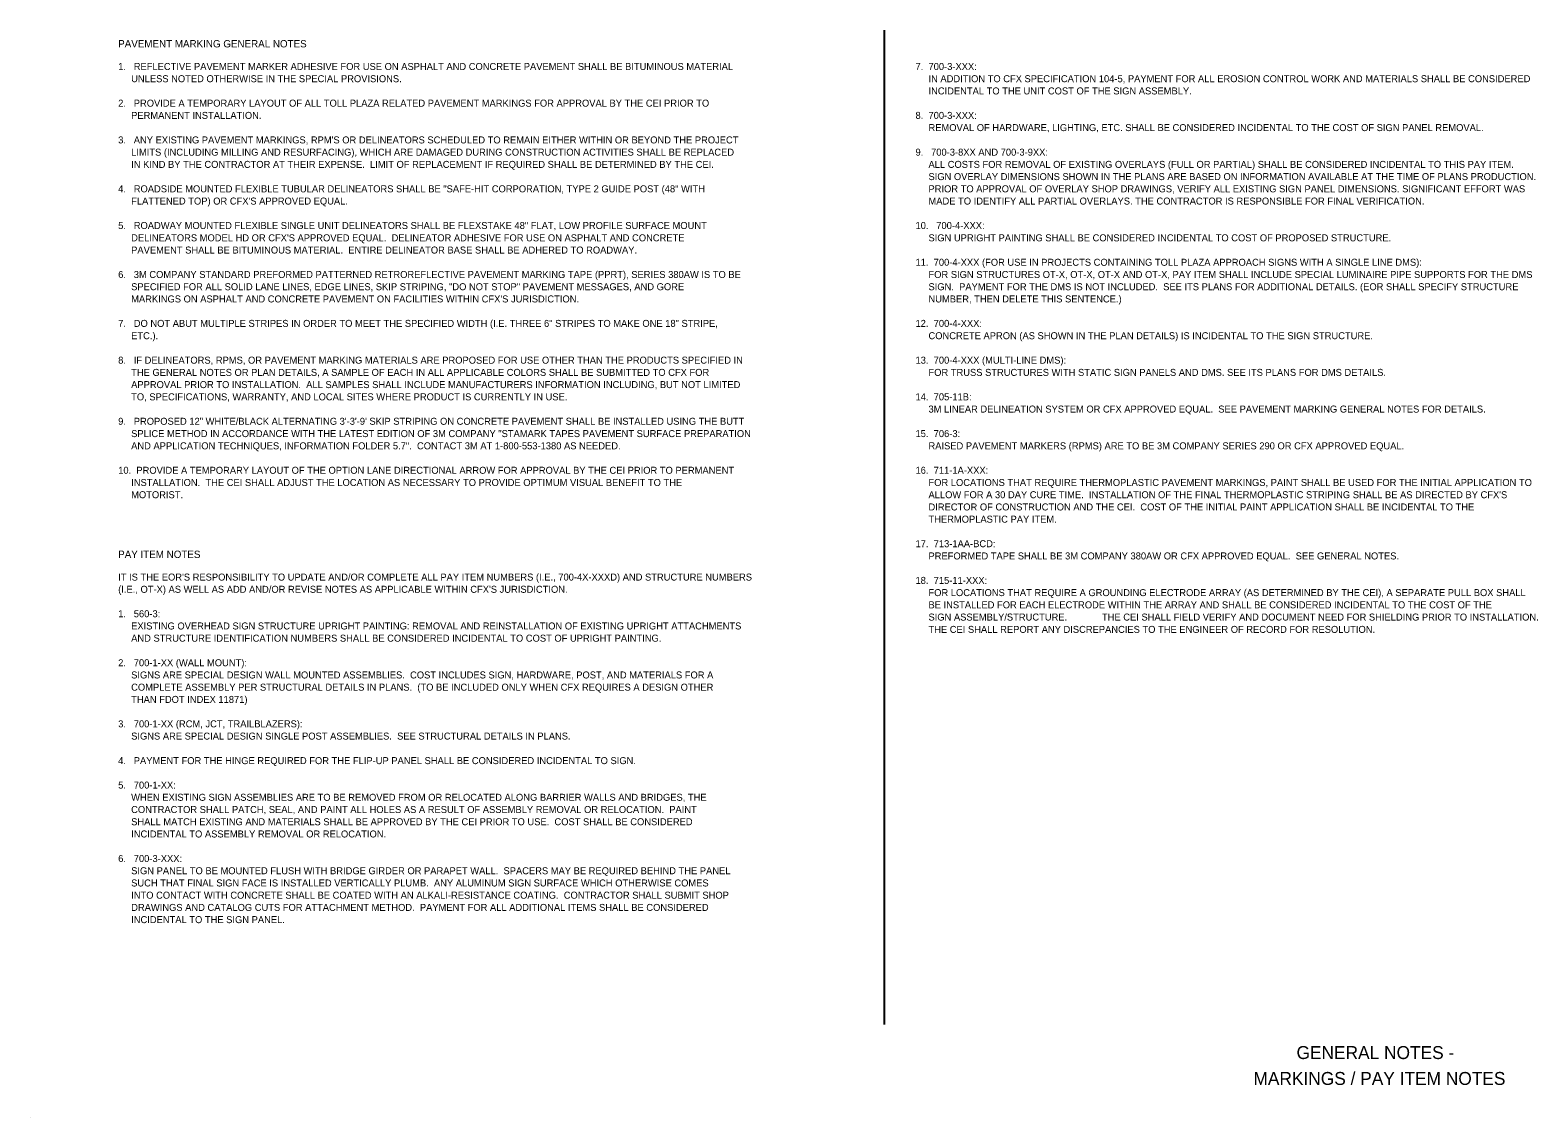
# Model space of a CAD drawing. Extents: x 2479959 to 2482822, y 3677554 to 3678604.
# Drawn here: x 2479959 to 2481415, y 3677554 to 3678604 of the extents above; entities that cross this region are included whole.
import ezdxf

# ---------------------------------------------------------------- set-up
doc = ezdxf.new("R2010")
doc.units = 0
for name, color, linetype in [('AdhocPoint_dp', 7, 'Continuous'), ('NonPlottingEle_dp', 7, 'Continuous'), ('TextLabel', 7, 'Continuous'), ('TextMisc', 7, 'Continuous')]:
    doc.layers.add(name, color=color, linetype=linetype)

msp = doc.modelspace()

# ---------------------------------------------------------------- linework, layer by layer
at = {"layer": 'AdhocPoint_dp'}
msp.add_line((2479959.3, 3677553.8), (2479959.3, 3677553.8), dxfattribs=at)
at = {"layer": 'NonPlottingEle_dp'}
msp.add_line((2480784.3, 3677643.8), (2480784.3, 3678603.8), dxfattribs=at)

# ---------------------------------------------------------------- texts
at = {"layer": 'TextLabel'}
for s, height, p in [('PAVEMENT MARKING GENERAL NOTES', 7.08, (2480044.3, 3678587.2)), ('1.   REFLECTIVE PAVEMENT MARKER ADHESIVE FOR USE ON ASPHALT AND CONCRETE PAVEMENT SHALL BE BITUMINOUS MATERIAL', 6.75, (2480044.3, 3678565.4)), ('7.  700-3-XXX:', 6.75, (2480814.3, 3678565.4)), ('     UNLESS NOTED OTHERWISE IN THE SPECIAL PROVISIONS.', 6.75, (2480044.3, 3678553.6)), ('     IN ADDITION TO CFX SPECIFICATION 104-5, PAYMENT FOR ALL EROSION CONTROL WORK AND MATERIALS SHALL BE CONSIDERED', 6.75, (2480814.3, 3678553.6)), ('     INCIDENTAL TO THE UNIT COST OF THE SIGN ASSEMBLY.', 6.75, (2480814.3, 3678541.8)), ('2.   PROVIDE A TEMPORARY LAYOUT OF ALL TOLL PLAZA RELATED PAVEMENT MARKINGS FOR APPROVAL BY THE CEI PRIOR TO', 6.75, (2480044.3, 3678530)), ('     PERMANENT INSTALLATION.', 6.75, (2480044.3, 3678518.2)), ('8.  700-3-XXX:', 6.75, (2480814.3, 3678518.2)), ('     REMOVAL OF HARDWARE, LIGHTING, ETC. SHALL BE CONSIDERED INCIDENTAL TO THE COST OF SIGN PANEL REMOVAL.', 6.75, (2480814.3, 3678506.4)), ("3.   ANY EXISTING PAVEMENT MARKINGS, RPM'S OR DELINEATORS SCHEDULED TO REMAIN EITHER WITHIN OR BEYOND THE PROJECT", 6.75, (2480044.3, 3678494.5)), ('     LIMITS (INCLUDING MILLING AND RESURFACING), WHICH ARE DAMAGED DURING CONSTRUCTION ACTIVITIES SHALL BE REPLACED', 6.75, (2480044.3, 3678482.7)), ('9.   700-3-8XX AND 700-3-9XX:', 6.75, (2480814.3, 3678482.7)), ('     IN KIND BY THE CONTRACTOR AT THEIR EXPENSE.  LIMIT OF REPLACEMENT IF REQUIRED SHALL BE DETERMINED BY THE CEI.', 6.75, (2480044.3, 3678470.9)), ('     ALL COSTS FOR REMOVAL OF EXISTING OVERLAYS (FULL OR PARTIAL) SHALL BE CONSIDERED INCIDENTAL TO THIS PAY ITEM. ', 6.75, (2480814.3, 3678470.9)), ('     SIGN OVERLAY DIMENSIONS SHOWN IN THE PLANS ARE BASED ON INFORMATION AVAILABLE AT THE TIME OF PLANS PRODUCTION.  ', 6.75, (2480814.3, 3678459.1)), ('4.   ROADSIDE MOUNTED FLEXIBLE TUBULAR DELINEATORS SHALL BE "SAFE-HIT CORPORATION, TYPE 2 GUIDE POST (48" WITH', 6.75, (2480044.3, 3678447.3)), ('     PRIOR TO APPROVAL OF OVERLAY SHOP DRAWINGS, VERIFY ALL EXISTING SIGN PANEL DIMENSIONS. SIGNIFICANT EFFORT WAS ', 6.75, (2480814.3, 3678447.3)), ("     FLATTENED TOP) OR CFX'S APPROVED EQUAL.", 6.75, (2480044.3, 3678435.5)), ('     MADE TO IDENTIFY ALL PARTIAL OVERLAYS. THE CONTRACTOR IS RESPONSIBLE FOR FINAL VERIFICATION. ', 6.75, (2480814.3, 3678435.5)), ('5.   ROADWAY MOUNTED FLEXIBLE SINGLE UNIT DELINEATORS SHALL BE FLEXSTAKE 48" FLAT, LOW PROFILE SURFACE MOUNT', 6.75, (2480044.3, 3678411.9)), ("     DELINEATORS MODEL HD OR CFX'S APPROVED EQUAL.  DELINEATOR ADHESIVE FOR USE ON ASPHALT AND CONCRETE", 6.75, (2480044.3, 3678400)), ('10.   700-4-XXX:', 6.75, (2480814.3, 3678411.9)), ('     SIGN UPRIGHT PAINTING SHALL BE CONSIDERED INCIDENTAL TO COST OF PROPOSED STRUCTURE.', 6.75, (2480814.3, 3678400)), ('     PAVEMENT SHALL BE BITUMINOUS MATERIAL.  ENTIRE DELINEATOR BASE SHALL BE ADHERED TO ROADWAY.', 6.75, (2480044.3, 3678388.2)), ('11.  700-4-XXX (FOR USE IN PROJECTS CONTAINING TOLL PLAZA APPROACH SIGNS WITH A SINGLE LINE DMS):', 6.75, (2480814.3, 3678376.4)), ('6.   3M COMPANY STANDARD PREFORMED PATTERNED RETROREFLECTIVE PAVEMENT MARKING TAPE (PPRT), SERIES 380AW IS TO BE', 6.75, (2480044.3, 3678364.6)), ('     FOR SIGN STRUCTURES OT-X, OT-X, OT-X AND OT-X, PAY ITEM SHALL INCLUDE SPECIAL LUMINAIRE PIPE SUPPORTS FOR THE DMS', 6.75, (2480814.3, 3678364.6)), ('     SPECIFIED FOR ALL SOLID LANE LINES, EDGE LINES, SKIP STRIPING, "DO NOT STOP" PAVEMENT MESSAGES, AND GORE', 6.75, (2480044.3, 3678352.8)), ('     SIGN.  PAYMENT FOR THE DMS IS NOT INCLUDED.  SEE ITS PLANS FOR ADDITIONAL DETAILS. (EOR SHALL SPECIFY STRUCTURE ', 6.75, (2480814.3, 3678352.8)), ("     MARKINGS ON ASPHALT AND CONCRETE PAVEMENT ON FACILITIES WITHIN CFX'S JURISDICTION.", 6.75, (2480044.3, 3678341)), ('     NUMBER, THEN DELETE THIS SENTENCE.)', 6.75, (2480814.3, 3678341)), ('7.   DO NOT ABUT MULTIPLE STRIPES IN ORDER TO MEET THE SPECIFIED WIDTH (I.E. THREE 6" STRIPES TO MAKE ONE 18" STRIPE,', 6.75, (2480044.3, 3678317.4)), ('12.  700-4-XXX:', 6.75, (2480814.3, 3678317.4)), ('     ETC.).', 6.75, (2480044.3, 3678305.5)), ('     CONCRETE APRON (AS SHOWN IN THE PLAN DETAILS) IS INCIDENTAL TO THE SIGN STRUCTURE. ', 6.75, (2480814.3, 3678305.5)), ('8.   IF DELINEATORS, RPMS, OR PAVEMENT MARKING MATERIALS ARE PROPOSED FOR USE OTHER THAN THE PRODUCTS SPECIFIED IN', 6.75, (2480044.3, 3678281.9)), ('     THE GENERAL NOTES OR PLAN DETAILS, A SAMPLE OF EACH IN ALL APPLICABLE COLORS SHALL BE SUBMITTED TO CFX FOR', 6.75, (2480044.3, 3678270.1)), ('13.  700-4-XXX (MULTI-LINE DMS):', 6.75, (2480814.3, 3678281.9)), ('     FOR TRUSS STRUCTURES WITH STATIC SIGN PANELS AND DMS. SEE ITS PLANS FOR DMS DETAILS.', 6.75, (2480814.3, 3678270.1)), ('     APPROVAL PRIOR TO INSTALLATION.  ALL SAMPLES SHALL INCLUDE MANUFACTURERS INFORMATION INCLUDING, BUT NOT LIMITED', 6.75, (2480044.3, 3678258.3)), ('     TO, SPECIFICATIONS, WARRANTY, AND LOCAL SITES WHERE PRODUCT IS CURRENTLY IN USE.', 6.75, (2480044.3, 3678246.5)), ('14.  705-11B:', 6.75, (2480814.3, 3678246.5)), ('     3M LINEAR DELINEATION SYSTEM OR CFX APPROVED EQUAL.  SEE PAVEMENT MARKING GENERAL NOTES FOR DETAILS.', 6.75, (2480814.3, 3678234.7)), ('9.   PROPOSED 12" WHITE/BLACK ALTERNATING 3\'-3\'-9\' SKIP STRIPING ON CONCRETE PAVEMENT SHALL BE INSTALLED USING THE BUTT', 6.75, (2480044.3, 3678222.9)), ('     SPLICE METHOD IN ACCORDANCE WITH THE LATEST EDITION OF 3M COMPANY "STAMARK TAPES PAVEMENT SURFACE PREPARATION', 6.75, (2480044.3, 3678211)), ('15.  706-3:', 6.75, (2480814.3, 3678211)), ('     AND APPLICATION TECHNIQUES, INFORMATION FOLDER 5.7".  CONTACT 3M AT 1-800-553-1380 AS NEEDED.', 6.75, (2480044.3, 3678199.2)), ('     RAISED PAVEMENT MARKERS (RPMS) ARE TO BE 3M COMPANY SERIES 290 OR CFX APPROVED EQUAL.', 6.75, (2480814.3, 3678199.2)), ('10.  PROVIDE A TEMPORARY LAYOUT OF THE OPTION LANE DIRECTIONAL ARROW FOR APPROVAL BY THE CEI PRIOR TO PERMANENT', 6.75, (2480044.3, 3678175.6)), ('16.  711-1A-XXX:', 6.75, (2480814.3, 3678175.6)), ('     INSTALLATION.  THE CEI SHALL ADJUST THE LOCATION AS NECESSARY TO PROVIDE OPTIMUM VISUAL BENEFIT TO THE', 6.75, (2480044.3, 3678163.8)), ('     FOR LOCATIONS THAT REQUIRE THERMOPLASTIC PAVEMENT MARKINGS, PAINT SHALL BE USED FOR THE INITIAL APPLICATION TO', 6.75, (2480814.3, 3678163.8)), ('     MOTORIST.', 6.75, (2480044.3, 3678152)), ("     ALLOW FOR A 30 DAY CURE TIME.  INSTALLATION OF THE FINAL THERMOPLASTIC STRIPING SHALL BE AS DIRECTED BY CFX'S", 6.75, (2480814.3, 3678152)), ('     DIRECTOR OF CONSTRUCTION AND THE CEI.  COST OF THE INITIAL PAINT APPLICATION SHALL BE INCIDENTAL TO THE', 6.75, (2480814.3, 3678140.2)), ('     THERMOPLASTIC PAY ITEM.', 6.75, (2480814.3, 3678128.4)), ('PAY ITEM NOTES', 7.08, (2480044.3, 3678094.3)), ('17.  713-1AA-BCD:', 6.75, (2480814.3, 3678104.7)), ('     PREFORMED TAPE SHALL BE 3M COMPANY 380AW OR CFX APPROVED EQUAL.  SEE GENERAL NOTES.', 6.75, (2480814.3, 3678092.9)), ("IT IS THE EOR'S RESPONSIBILITY TO UPDATE AND/OR COMPLETE ALL PAY ITEM NUMBERS (I.E., 700-4X-XXXD) AND STRUCTURE NUMBERS", 6.75, (2480044.3, 3678072.5)), ('18.  715-11-XXX:', 6.75, (2480814.3, 3678069.3)), ("(I.E., OT-X) AS WELL AS ADD AND/OR REVISE NOTES AS APPLICABLE WITHIN CFX'S JURISDICTION.", 6.75, (2480044.3, 3678060.7)), ('     FOR LOCATIONS THAT REQUIRE A GROUNDING ELECTRODE ARRAY (AS DETERMINED BY THE CEI), A SEPARATE PULL BOX SHALL ', 6.75, (2480814.3, 3678057.5)), ('1.   560-3:', 6.75, (2480044.3, 3678037.1)), ('     BE INSTALLED FOR EACH ELECTRODE WITHIN THE ARRAY AND SHALL BE CONSIDERED INCIDENTAL TO THE COST OF THE ', 6.75, (2480814.3, 3678045.7)), ('     EXISTING OVERHEAD SIGN STRUCTURE UPRIGHT PAINTING: REMOVAL AND REINSTALLATION OF EXISTING UPRIGHT ATTACHMENTS', 6.75, (2480044.3, 3678025.3)), ('     THE CEI SHALL REPORT ANY DISCREPANCIES TO THE ENGINEER OF RECORD FOR RESOLUTION.', 6.75, (2480814.3, 3678022)), ('     SIGN ASSEMBLY/STRUCTURE.  ', 6.75, (2480814.3, 3678033.9)), ('THE CEI SHALL FIELD VERIFY AND DOCUMENT NEED FOR SHIELDING PRIOR TO INSTALLATION.  ', 6.75, (2480994.4, 3678033.9)), ('     AND STRUCTURE IDENTIFICATION NUMBERS SHALL BE CONSIDERED INCIDENTAL TO COST OF UPRIGHT PAINTING.', 6.75, (2480044.3, 3678013.5)), ('2.   700-1-XX (WALL MOUNT):', 6.75, (2480044.3, 3677989.8)), ('     SIGNS ARE SPECIAL DESIGN WALL MOUNTED ASSEMBLIES.  COST INCLUDES SIGN, HARDWARE, POST, AND MATERIALS FOR A', 6.75, (2480044.3, 3677978)), ('     COMPLETE ASSEMBLY PER STRUCTURAL DETAILS IN PLANS.  (TO BE INCLUDED ONLY WHEN CFX REQUIRES A DESIGN OTHER', 6.75, (2480044.3, 3677966.2)), ('     THAN FDOT INDEX 11871)', 6.75, (2480044.3, 3677954.4)), ('3.   700-1-XX (RCM, JCT, TRAILBLAZERS):', 6.75, (2480044.3, 3677930.8)), ('     SIGNS ARE SPECIAL DESIGN SINGLE POST ASSEMBLIES.  SEE STRUCTURAL DETAILS IN PLANS.', 6.75, (2480044.3, 3677919)), ('4.   PAYMENT FOR THE HINGE REQUIRED FOR THE FLIP-UP PANEL SHALL BE CONSIDERED INCIDENTAL TO SIGN.', 6.75, (2480044.3, 3677895.3)), ('5.   700-1-XX:', 6.75, (2480044.3, 3677871.7)), ('     WHEN EXISTING SIGN ASSEMBLIES ARE TO BE REMOVED FROM OR RELOCATED ALONG BARRIER WALLS AND BRIDGES, THE', 6.75, (2480044.3, 3677859.9)), ('     CONTRACTOR SHALL PATCH, SEAL, AND PAINT ALL HOLES AS A RESULT OF ASSEMBLY REMOVAL OR RELOCATION.  PAINT', 6.75, (2480044.3, 3677848.1)), ('     SHALL MATCH EXISTING AND MATERIALS SHALL BE APPROVED BY THE CEI PRIOR TO USE.  COST SHALL BE CONSIDERED', 6.75, (2480044.3, 3677836.3)), ('     INCIDENTAL TO ASSEMBLY REMOVAL OR RELOCATION.', 6.75, (2480044.3, 3677824.5)), ('6.   700-3-XXX:', 6.75, (2480044.3, 3677800.8)), ('     SIGN PANEL TO BE MOUNTED FLUSH WITH BRIDGE GIRDER OR PARAPET WALL.  SPACERS MAY BE REQUIRED BEHIND THE PANEL', 6.75, (2480044.3, 3677789)), ('     SUCH THAT FINAL SIGN FACE IS INSTALLED VERTICALLY PLUMB.  ANY ALUMINUM SIGN SURFACE WHICH OTHERWISE COMES', 6.75, (2480044.3, 3677777.2)), ('     INTO CONTACT WITH CONCRETE SHALL BE COATED WITH AN ALKALI-RESISTANCE COATING.  CONTRACTOR SHALL SUBMIT SHOP', 6.75, (2480044.3, 3677765.4)), ('     DRAWINGS AND CATALOG CUTS FOR ATTACHMENT METHOD.  PAYMENT FOR ALL ADDITIONAL ITEMS SHALL BE CONSIDERED', 6.75, (2480044.3, 3677753.6)), ('     INCIDENTAL TO THE SIGN PANEL.', 6.75, (2480044.3, 3677741.8))]:
    msp.add_text(s, height=height, dxfattribs=at).set_placement(p)
at = {"layer": 'TextMisc'}
for s, p in [('    GENERAL NOTES -     ', (2481163.7, 3677610.6)), ('MARKINGS / PAY ITEM NOTES', (2481140.7, 3677585.6))]:
    msp.add_text(s, height=12.5, rotation=360, dxfattribs=at).set_placement(p)

doc.saveas('drawing.dxf')
